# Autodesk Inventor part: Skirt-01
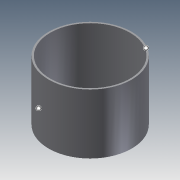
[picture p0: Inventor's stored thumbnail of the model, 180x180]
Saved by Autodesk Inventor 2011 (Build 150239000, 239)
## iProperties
Created: 2010-06
Part Number: Skirt-01
Document SubType Name: Modeling
Designer: mklassen
Density: 1 g/cm^3
OD: 24.000 in
THK: 0.500 in
LEN: 1.500 ft
SKVOFS: 6.000 in
Author: mklassen
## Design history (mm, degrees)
sketch "skSkirt"
  geometry: C1 r 317.5 at (0, 0); C2 r 304.8 at (0, 0); 1 further point
  constraints: 2 centre point, 1 coincident
  dimensions: "d0" = 609.6 diameter of C2 (derived); "d1" = 12.7 radial gap between concentric circles of C1 C2 (derived)
extrude "Extrusion1" new body sketch "skSkirt" stored distance "d2" = 457.2 (derived); taper "d3" = 0 deg
body "Solid1"
other parameters: "d4" = 152.4 (derived), "d5" = 0
